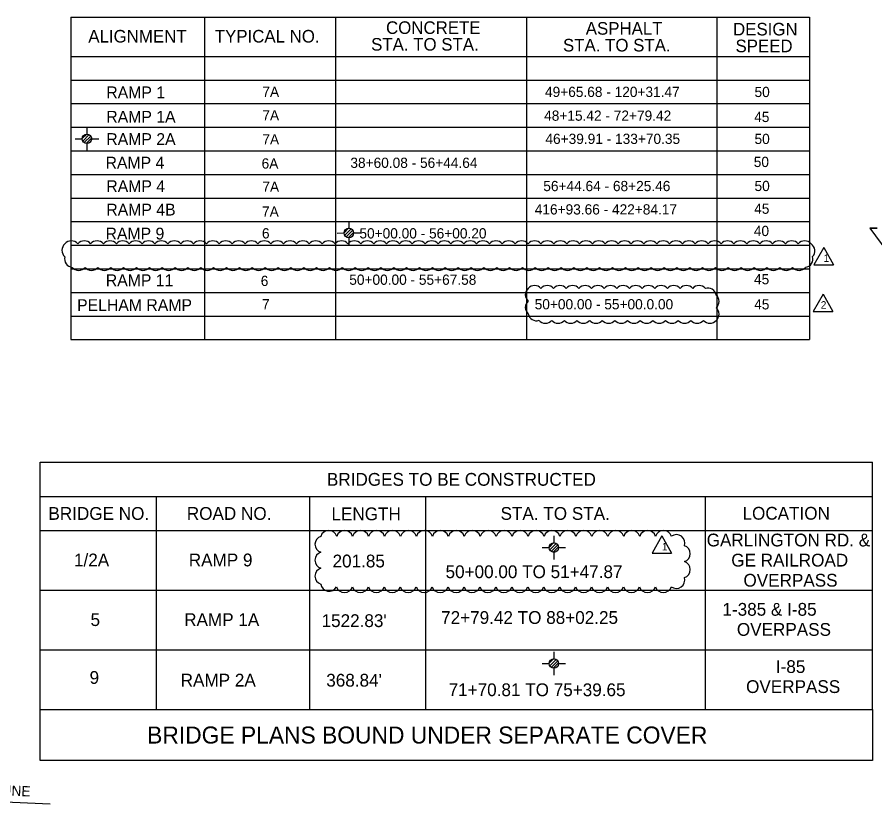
# Model space of a CAD drawing. Extents: x 4649 to 5578, y 4853 to 5383.
# Drawn here: x 5130 to 5230.6, y 5069.6 to 5161.9 of the extents above; entities that cross this region are included whole.
import ezdxf

# ---------------------------------------------------------------- set-up
doc = ezdxf.new("R2010")
doc.units = 0
for name, color, linetype in [('Level 1', 7, 'Continuous'), ('Level 20', 7, 'Continuous'), ('Level 3', 7, 'Continuous'), ('RD_EX_SU_Pole', 7, 'Continuous'), ('RD_SHT_TX', 7, 'Continuous'), ('RD_SHT_Typical', 7, 'Continuous'), ('RD_Sketch1', 7, 'Continuous'), ('RD_TX_TitleSht', 7, 'Continuous'), ('RD_TX_TypSect', 7, 'Continuous'), ('RD_XS_Pave', 7, 'Continuous')]:
    doc.layers.add(name, color=color, linetype=linetype)

# ---------------------------------------------------------------- blocks, each defined once
blk = doc.blocks.new('SUE_TFP')
at = {"layer": 'RD_EX_SU_Pole'}
for p, q in [((0, 5.5), (0, 2.22)), ((-2.21, 0.13), (-0.13, 2.21)), ((-1.96, -1.03), (1.03, 1.96)), ((-1.31, -1.79), (1.79, 1.31)), ((-0.3, -2.2), (2.2, 0.3)), ((2.22, 0), (5.53, 0.01)), ((-5.53, -0.01), (-2.22, 0)), ((0, -2.22), (0, -5.5))]:
    blk.add_line(p, q, dxfattribs=at)
blk.add_circle((0, 0), 2.22, dxfattribs=at)

msp = doc.modelspace()

# ---------------------------------------------------------------- linework, layer by layer
at = {"layer": 'Level 1'}
for p, q in [((5136.26, 5161.89), (5222.91, 5161.89)), ((5136.26, 5161.89), (5136.26, 5157.27)), ((5151.96, 5161.89), (5151.96, 5157.27)), ((5167.31, 5161.89), (5167.31, 5157.27)), ((5189.73, 5161.89), (5189.73, 5157.27)), ((5212.01, 5161.89), (5212.01, 5157.27)), ((5222.91, 5161.89), (5222.91, 5157.27)), ((5136.26, 5157.27), (5222.91, 5157.27)), ((5167.31, 5157.27), (5167.31, 5124.05)), ((5189.73, 5157.27), (5189.73, 5124.05)), ((5212.01, 5157.27), (5212.01, 5124.05))]:
    msp.add_line(p, q, dxfattribs=at)
at = {"layer": 'Level 20'}
msp.add_lwpolyline([(5132.69, 5080.65), (5230.29, 5080.65), (5230.29, 5074.65), (5132.69, 5074.65)], close=True, dxfattribs=at)
at = {"layer": 'Level 3'}
for p, q in [((5132.69, 5109.65), (5230.29, 5109.65)), ((5132.69, 5080.65), (5132.69, 5109.65)), ((5230.29, 5080.65), (5230.29, 5109.65)), ((5132.69, 5105.65), (5230.29, 5105.65)), ((5164.29, 5080.65), (5164.29, 5105.65)), ((5177.89, 5080.65), (5177.89, 5105.65)), ((5210.69, 5080.65), (5210.69, 5105.65)), ((5132.69, 5101.65), (5230.29, 5101.65)), ((5132.69, 5094.65), (5230.29, 5094.65)), ((5132.69, 5087.65), (5230.29, 5087.65)), ((5132.69, 5080.65), (5230.29, 5080.65))]:
    msp.add_line(p, q, dxfattribs=at)
at = {"layer": 'RD_SHT_TX'}
for p, q in [((5224.56, 5134.87), (5223.42, 5132.84)), ((5224.56, 5134.87), (5225.7, 5132.84)), ((5223.42, 5132.84), (5225.7, 5132.84)), ((5224.48, 5129.38), (5223.34, 5127.35)), ((5224.48, 5129.38), (5225.62, 5127.35)), ((5223.34, 5127.35), (5225.62, 5127.35)), ((5205.59, 5101.02), (5204.45, 5098.99)), ((5205.59, 5101.02), (5206.73, 5098.99)), ((5204.45, 5098.99), (5206.73, 5098.99))]:
    msp.add_line(p, q, dxfattribs=at)
for centre, radius, start, end in [((5136.22, 5134.53), 0.985, 130, 230), ((5136.34, 5134.65), 0.985, 40, 140), ((5137.85, 5134.65), 0.985, 40, 140), ((5139.35, 5134.65), 0.985, 40, 140), ((5140.86, 5134.65), 0.985, 40, 140), ((5142.37, 5134.65), 0.985, 40, 140), ((5143.88, 5134.65), 0.985, 40, 140), ((5145.39, 5134.65), 0.985, 40, 140), ((5146.9, 5134.65), 0.985, 40, 140), ((5148.41, 5134.65), 0.985, 40, 140), ((5149.92, 5134.65), 0.985, 40, 140), ((5151.42, 5134.65), 0.985, 40, 140), ((5152.93, 5134.65), 0.985, 40, 140), ((5154.44, 5134.65), 0.985, 40, 140), ((5155.95, 5134.65), 0.985, 40, 140), ((5157.46, 5134.65), 0.985, 40, 140), ((5158.97, 5134.65), 0.985, 40, 140), ((5160.48, 5134.65), 0.985, 40, 140), ((5161.98, 5134.65), 0.985, 40, 140), ((5163.49, 5134.65), 0.985, 40, 140), ((5165, 5134.65), 0.985, 40, 140), ((5166.51, 5134.65), 0.985, 40, 140), ((5168.02, 5134.65), 0.985, 40, 140), ((5169.53, 5134.65), 0.985, 40, 140), ((5171.04, 5134.65), 0.985, 40, 140), ((5172.55, 5134.65), 0.985, 40, 140), ((5174.05, 5134.65), 0.985, 40, 140), ((5175.56, 5134.65), 0.985, 40, 140), ((5177.07, 5134.65), 0.985, 40, 140), ((5178.58, 5134.65), 0.985, 40, 140), ((5180.09, 5134.65), 0.985, 40, 140), ((5181.6, 5134.65), 0.985, 40, 140), ((5183.11, 5134.65), 0.985, 40, 140), ((5184.61, 5134.65), 0.985, 40, 140), ((5186.12, 5134.65), 0.985, 40, 140), ((5187.63, 5134.65), 0.985, 40, 140), ((5189.14, 5134.65), 0.985, 40, 140), ((5190.65, 5134.65), 0.985, 40, 140), ((5192.16, 5134.65), 0.985, 40, 140), ((5193.67, 5134.65), 0.985, 40, 140), ((5195.18, 5134.65), 0.985, 40, 140), ((5196.68, 5134.65), 0.985, 40, 140), ((5198.19, 5134.65), 0.985, 40, 140), ((5199.7, 5134.65), 0.985, 40, 140), ((5201.21, 5134.65), 0.985, 40, 140), ((5202.72, 5134.65), 0.985, 40, 140), ((5204.23, 5134.65), 0.985, 40, 140), ((5205.74, 5134.65), 0.985, 40, 140), ((5207.24, 5134.65), 0.985, 40, 140), ((5208.75, 5134.65), 0.985, 40, 140), ((5210.26, 5134.65), 0.985, 40, 140), ((5211.77, 5134.65), 0.985, 40, 140), ((5213.28, 5134.65), 0.985, 40, 140), ((5214.79, 5134.65), 0.985, 40, 140), ((5216.3, 5134.65), 0.985, 40, 140), ((5217.81, 5134.65), 0.985, 40, 140), ((5219.31, 5134.65), 0.985, 40, 140), ((5220.82, 5134.65), 0.985, 40, 140), ((5222.33, 5134.65), 0.985, 40, 140), ((5222.54, 5134.46), 0.984, 316.6397, 56.6397), ((5136.53, 5133.51), 0.985, 164.3047, 264.3047), ((5222.32, 5133.51), 0.984, 276.4906, 16.4906), ((5137.19, 5133.16), 0.985, 220, 320), ((5138.7, 5133.16), 0.985, 220, 320), ((5140.2, 5133.16), 0.985, 220, 320), ((5141.71, 5133.16), 0.985, 220, 320), ((5143.22, 5133.16), 0.985, 220, 320), ((5144.73, 5133.16), 0.985, 220, 320), ((5146.24, 5133.16), 0.985, 220, 320), ((5147.75, 5133.16), 0.985, 220, 320), ((5149.26, 5133.16), 0.985, 220, 320), ((5150.77, 5133.16), 0.985, 220, 320), ((5152.27, 5133.16), 0.985, 220, 320), ((5153.78, 5133.16), 0.985, 220, 320), ((5155.29, 5133.16), 0.985, 220, 320), ((5156.8, 5133.16), 0.985, 220, 320), ((5158.31, 5133.16), 0.985, 220, 320), ((5159.82, 5133.16), 0.985, 220, 320), ((5161.33, 5133.16), 0.985, 220, 320), ((5162.83, 5133.16), 0.985, 220, 320), ((5164.34, 5133.16), 0.985, 220, 320), ((5165.85, 5133.16), 0.985, 220, 320), ((5167.36, 5133.16), 0.985, 220, 320), ((5168.87, 5133.16), 0.985, 220, 320), ((5170.38, 5133.16), 0.985, 220, 320), ((5171.89, 5133.16), 0.985, 220, 320), ((5173.4, 5133.16), 0.985, 220, 320), ((5174.9, 5133.16), 0.985, 220, 320), ((5176.41, 5133.16), 0.985, 220, 320), ((5177.92, 5133.16), 0.985, 220, 320), ((5179.43, 5133.16), 0.985, 220, 320), ((5180.94, 5133.16), 0.985, 220, 320), ((5182.45, 5133.16), 0.985, 220, 320), ((5183.96, 5133.16), 0.985, 220, 320), ((5185.46, 5133.16), 0.985, 220, 320), ((5186.97, 5133.16), 0.985, 220, 320), ((5188.48, 5133.16), 0.985, 220, 320), ((5189.99, 5133.16), 0.985, 220, 320), ((5191.5, 5133.16), 0.985, 220, 320), ((5193.01, 5133.16), 0.985, 220, 320), ((5194.52, 5133.16), 0.985, 220, 320), ((5196.03, 5133.16), 0.985, 220, 320), ((5197.53, 5133.16), 0.985, 220, 320), ((5199.04, 5133.16), 0.985, 220, 320), ((5200.55, 5133.16), 0.985, 220, 320), ((5202.06, 5133.16), 0.985, 220, 320), ((5203.57, 5133.16), 0.985, 220, 320), ((5205.08, 5133.16), 0.985, 220, 320), ((5206.59, 5133.16), 0.985, 220, 320), ((5208.09, 5133.16), 0.985, 220, 320), ((5209.6, 5133.16), 0.985, 220, 320), ((5211.11, 5133.16), 0.985, 220, 320), ((5212.62, 5133.16), 0.985, 220, 320), ((5214.13, 5133.16), 0.985, 220, 320), ((5215.64, 5133.16), 0.985, 220, 320), ((5217.15, 5133.16), 0.985, 220, 320), ((5218.66, 5133.16), 0.985, 220, 320), ((5220.16, 5133.16), 0.985, 220, 320), ((5221.67, 5133.16), 0.985, 220, 320), ((5190.66, 5129.43), 0.968, 40, 140), ((5192.14, 5129.43), 0.968, 40, 140), ((5193.63, 5129.43), 0.968, 40, 140), ((5195.11, 5129.43), 0.968, 40, 140), ((5196.59, 5129.43), 0.968, 40, 140), ((5198.08, 5129.43), 0.968, 40, 140), ((5199.56, 5129.43), 0.968, 40, 140), ((5201.04, 5129.43), 0.968, 40, 140), ((5202.53, 5129.43), 0.968, 40, 140), ((5204.01, 5129.43), 0.968, 40, 140), ((5205.49, 5129.43), 0.968, 40, 140), ((5206.98, 5129.43), 0.968, 40, 140), ((5208.46, 5129.43), 0.968, 40, 140), ((5209.94, 5129.43), 0.968, 40, 140), ((5190.54, 5129.31), 0.968, 130, 230), ((5210.99, 5129.13), 0.968, 8.4921, 108.4921), ((5211.32, 5128.54), 0.968, 310, 50), ((5190.54, 5127.83), 0.968, 130, 230), ((5211.32, 5127.05), 0.968, 310, 50), ((5190.88, 5127.23), 0.968, 188.4921, 288.4921), ((5191.92, 5126.93), 0.968, 220, 320), ((5193.41, 5126.93), 0.968, 220, 320), ((5194.89, 5126.93), 0.968, 220, 320), ((5196.37, 5126.93), 0.968, 220, 320), ((5197.86, 5126.93), 0.968, 220, 320), ((5199.34, 5126.93), 0.968, 220, 320), ((5200.82, 5126.93), 0.968, 220, 320), ((5202.31, 5126.93), 0.968, 220, 320), ((5203.79, 5126.93), 0.968, 220, 320), ((5205.27, 5126.93), 0.968, 220, 320), ((5206.76, 5126.93), 0.968, 220, 320), ((5208.24, 5126.93), 0.968, 220, 320), ((5209.72, 5126.93), 0.968, 220, 320), ((5211.21, 5126.93), 0.968, 220, 320), ((5166.52, 5100.67), 0.98, 17.5, 162.5), ((5168.39, 5100.67), 0.98, 17.5, 162.5), ((5170.26, 5100.67), 0.98, 17.5, 162.5), ((5172.13, 5100.67), 0.98, 17.5, 162.5), ((5174, 5100.67), 0.98, 17.5, 162.5), ((5175.87, 5100.67), 0.98, 17.5, 162.5), ((5177.74, 5100.67), 0.98, 17.5, 162.5), ((5179.61, 5100.67), 0.98, 17.5, 162.5), ((5181.48, 5100.67), 0.98, 17.5, 162.5), ((5183.35, 5100.67), 0.98, 17.5, 162.5), ((5185.22, 5100.67), 0.98, 17.5, 162.5), ((5187.09, 5100.67), 0.98, 17.5, 162.5), ((5188.96, 5100.67), 0.98, 17.5, 162.5), ((5190.83, 5100.67), 0.98, 17.5, 162.5), ((5192.7, 5100.67), 0.98, 17.5, 162.5), ((5194.57, 5100.67), 0.98, 17.5, 162.5), ((5196.44, 5100.67), 0.98, 17.5, 162.5), ((5198.31, 5100.67), 0.98, 17.5, 162.5), ((5200.18, 5100.67), 0.98, 17.5, 162.5), ((5202.05, 5100.67), 0.98, 17.5, 162.5), ((5203.92, 5100.67), 0.98, 17.5, 162.5), ((5205.78, 5100.67), 0.98, 17.5, 162.5), ((5207.3, 5100.18), 0.981, 341.3136, 126.3136), ((5165.88, 5100.03), 0.98, 107.5, 252.5), ((5165.88, 5098.16), 0.98, 107.5, 252.5), ((5207.94, 5098.93), 0.98, 287.5, 72.5), ((5165.88, 5096.29), 0.98, 107.5, 252.5), ((5207.94, 5097.06), 0.98, 287.5, 72.5), ((5207.29, 5095.83), 0.98, 232.3066, 17.3066), ((5166.55, 5095.5), 0.98, 188.2303, 333.2303), ((5168.36, 5095.35), 0.98, 197.5, 342.5), ((5170.23, 5095.35), 0.98, 197.5, 342.5), ((5172.1, 5095.35), 0.98, 197.5, 342.5), ((5173.97, 5095.35), 0.98, 197.5, 342.5), ((5175.84, 5095.35), 0.98, 197.5, 342.5), ((5177.71, 5095.35), 0.98, 197.5, 342.5), ((5179.58, 5095.35), 0.98, 197.5, 342.5), ((5181.45, 5095.35), 0.98, 197.5, 342.5), ((5183.32, 5095.35), 0.98, 197.5, 342.5), ((5185.19, 5095.35), 0.98, 197.5, 342.5), ((5187.06, 5095.35), 0.98, 197.5, 342.5), ((5188.93, 5095.35), 0.98, 197.5, 342.5), ((5190.8, 5095.35), 0.98, 197.5, 342.5), ((5192.67, 5095.35), 0.98, 197.5, 342.5), ((5194.54, 5095.35), 0.98, 197.5, 342.5), ((5196.41, 5095.35), 0.98, 197.5, 342.5), ((5198.28, 5095.35), 0.98, 197.5, 342.5), ((5200.15, 5095.35), 0.98, 197.5, 342.5), ((5202.02, 5095.35), 0.98, 197.5, 342.5), ((5203.89, 5095.35), 0.98, 197.5, 342.5), ((5205.76, 5095.35), 0.98, 197.5, 342.5)]:
    msp.add_arc(centre, radius, start, end, dxfattribs=at)
at = {"layer": 'RD_SHT_Typical'}
for q in [(5231.97, 5134.44), (5230.83, 5137.13)]:
    msp.add_line((5229.96, 5137.13), q, dxfattribs=at)
at = {"layer": 'RD_Sketch1'}
msp.add_line((5111.76, 5070.58), (5133.85, 5069.57), dxfattribs=at)
at = {"layer": 'RD_TX_TitleSht'}
msp.add_line((5146.29, 5105.65), (5146.29, 5080.65), dxfattribs=at)
at = {"layer": 'RD_TX_TypSect'}
for p, q in [((5136.26, 5157.27), (5136.26, 5124.05)), ((5151.96, 5157.27), (5151.96, 5124.05)), ((5222.91, 5157.27), (5222.91, 5124.05)), ((5136.26, 5154.5), (5222.91, 5154.5)), ((5136.26, 5151.74), (5222.91, 5151.74)), ((5136.26, 5148.97), (5222.91, 5148.97)), ((5136.26, 5146.2), (5222.91, 5146.2)), ((5136.26, 5143.43), (5222.91, 5143.43)), ((5136.26, 5140.66), (5222.91, 5140.66)), ((5136.26, 5137.89), (5222.91, 5137.89)), ((5136.26, 5135.12), (5222.91, 5135.12)), ((5136.26, 5132.35), (5222.91, 5132.35)), ((5136.26, 5129.58), (5222.91, 5129.58)), ((5136.26, 5126.81), (5222.91, 5126.81)), ((5136.26, 5124.05), (5222.91, 5124.05))]:
    msp.add_line(p, q, dxfattribs=at)
at = {"layer": 'RD_XS_Pave'}
for p, q in [((5230.83, 5137.13), (5229.96, 5137.13)), ((5229.96, 5137.13), (5231.97, 5134.44))]:
    msp.add_line(p, q, dxfattribs=at)

# ---------------------------------------------------------------- block references
at = {"layer": 'Level 3', "xscale": 0.24999999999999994, "yscale": 0.24999999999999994}
for p in [(5138.17, 5147.61), (5168.88, 5136.56), (5192.92, 5099.64), (5192.92, 5086.04)]:
    msp.add_blockref('SUE_TFP', p, dxfattribs=at)

# ---------------------------------------------------------------- texts
at = {"layer": 'Level 3'}
for s, height, p in [('BRIDGES TO BE CONSTRUCTED', 1.5, (5166.31, 5106.9)), ('BRIDGE NO.', 1.5, (5133.65, 5102.9)), ('ROAD NO.', 1.5, (5149.88, 5102.9)), ('LENGTH', 1.5, (5166.84, 5102.85)), ('STA. TO STA.', 1.5, (5186.67, 5102.9)), ('LOCATION', 1.5, (5215.04, 5102.92)), ('GARLINGTON RD. & ', 1.5, (5210.84, 5099.78)), ('1/2A', 1.5, (5136.65, 5097.44)), ('RAMP 9', 1.5, (5150.11, 5097.44)), ('201.85', 1.5, (5166.97, 5097.32)), ('GE RAILROAD', 1.5, (5213.72, 5097.42)), ('50+00.00 TO 51+47.87', 1.5, (5180.22, 5096.06)), ('OVERPASS', 1.5, (5215.15, 5095.06)), ('1-385 & I-85 ', 1.5, (5212.69, 5091.65)), ('72+79.42 TO 88+02.25', 1.5, (5179.7, 5090.69)), ('5', 1.5, (5138.59, 5090.44)), ('RAMP 1A', 1.5, (5149.57, 5090.44)), ("1522.83'", 1.5, (5165.68, 5090.32)), ('OVERPASS', 1.5, (5214.38, 5089.29)), ('BRIDGE PLANS BOUND UNDER SEPARATE COVER', 2, (5145.23, 5076.65))]:
    msp.add_text(s, height=height, rotation=360, dxfattribs=at).set_placement(p)
for s, p in [('I-85 ', (5218.95, 5084.93)), ('9', (5138.48, 5083.65)), ('RAMP 2A', (5149.16, 5083.34)), ("368.84'", (5166.23, 5083.33)), ('OVERPASS', (5215.46, 5082.58)), ('71+70.81 TO 75+39.65', (5180.58, 5082.21))]:
    msp.add_text(s, height=1.5, dxfattribs=at).set_placement(p)
at = {"layer": 'RD_SHT_TX'}
for s, p in [('1', (5224.56, 5133.17)), ('2', (5224.22, 5127.68)), ('1', (5205.59, 5099.32))]:
    msp.add_text(s, height=0.88, dxfattribs=at).set_placement(p)
at = {"layer": 'RD_TX_TypSect'}
for s, height, p in [('CONCRETE', 1.477, (5173.24, 5159.92)), ('ASPHALT', 1.477, (5196.66, 5159.83)), ('DESIGN', 1.477, (5213.93, 5159.74)), ('ALIGNMENT', 1.477, (5138.33, 5158.91)), ('TYPICAL NO.', 1.4768, (5153.16, 5158.91)), ('STA. TO STA.', 1.4768, (5171.49, 5157.96)), ('STA. TO STA.', 1.4768, (5193.99, 5157.86)), ('SPEED', 1.477, (5214.22, 5157.77)), ('RAMP 1', 1.384, (5140.44, 5152.37)), ('7A', 1.2, (5158.74, 5152.53)), ('49+65.68 - 120+31.47', 1.2, (5191.88, 5152.52)), ('50', 1.2, (5216.45, 5152.51)), ('RAMP 1A', 1.384, (5140.44, 5149.51)), ('7A', 1.2, (5158.74, 5149.77)), ('48+15.42 - 72+79.42', 1.2, (5191.78, 5149.73)), ('45', 1.2, (5216.41, 5149.58)), ('RAMP 2A', 1.384, (5140.44, 5146.89)), ('7A', 1.2, (5158.74, 5146.95)), ('46+39.91 - 133+70.35', 1.2, (5191.93, 5147.01)), ('50', 1.2, (5216.45, 5147)), ('RAMP 4', 1.384, (5140.35, 5144.12)), ('6A', 1.2, (5158.65, 5144.12)), ('38+60.08 - 56+44.64', 1.2, (5169.06, 5144.2)), ('50', 1.2, (5216.36, 5144.3)), ('RAMP 4', 1.384, (5140.44, 5141.36)), ('7A', 1.2, (5158.74, 5141.39)), ('56+44.64 - 68+25.46', 1.2, (5191.68, 5141.47)), ('50', 1.2, (5216.45, 5141.48)), ('RAMP 4B', 1.384, (5140.44, 5138.61)), ('7A', 1.2, (5158.7, 5138.47)), ('416+93.66 - 422+84.17', 1.2, (5190.68, 5138.73)), ('45', 1.2, (5216.41, 5138.81)), ('40', 1.2, (5216.37, 5136.2)), ('RAMP 9', 1.384, (5140.35, 5135.8)), ('6', 1.2, (5158.69, 5135.92)), ('50+00.00 - 56+00.20', 1.2, (5170.12, 5135.92)), ('RAMP 11', 1.384, (5140.38, 5130.32)), ('6', 1.2, (5158.55, 5130.34)), ('50+00.00 - 55+67.58', 1.2, (5168.93, 5130.48)), ('45', 1.2, (5216.39, 5130.54)), ('PELHAM RAMP', 1.3845, (5137.01, 5127.41)), ('7', 1.2, (5158.7, 5127.6)), ('50+00.00 - 55+00.0.00', 1.2, (5190.67, 5127.6)), ('45', 1.2, (5216.41, 5127.59))]:
    msp.add_text(s, height=height, dxfattribs=at).set_placement(p)
msp.add_text('GROUND LINE', height=1.2, rotation=357.3905, dxfattribs=at).set_placement((5120.39, 5070.94))

doc.saveas('drawing.dxf')
